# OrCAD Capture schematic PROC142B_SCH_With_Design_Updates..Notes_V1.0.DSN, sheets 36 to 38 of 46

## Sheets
36 36. MCU HEADER: size C; title: SOC-MCU DOMAIN IO, OSC0 AND SOC-MCU IO HEADER
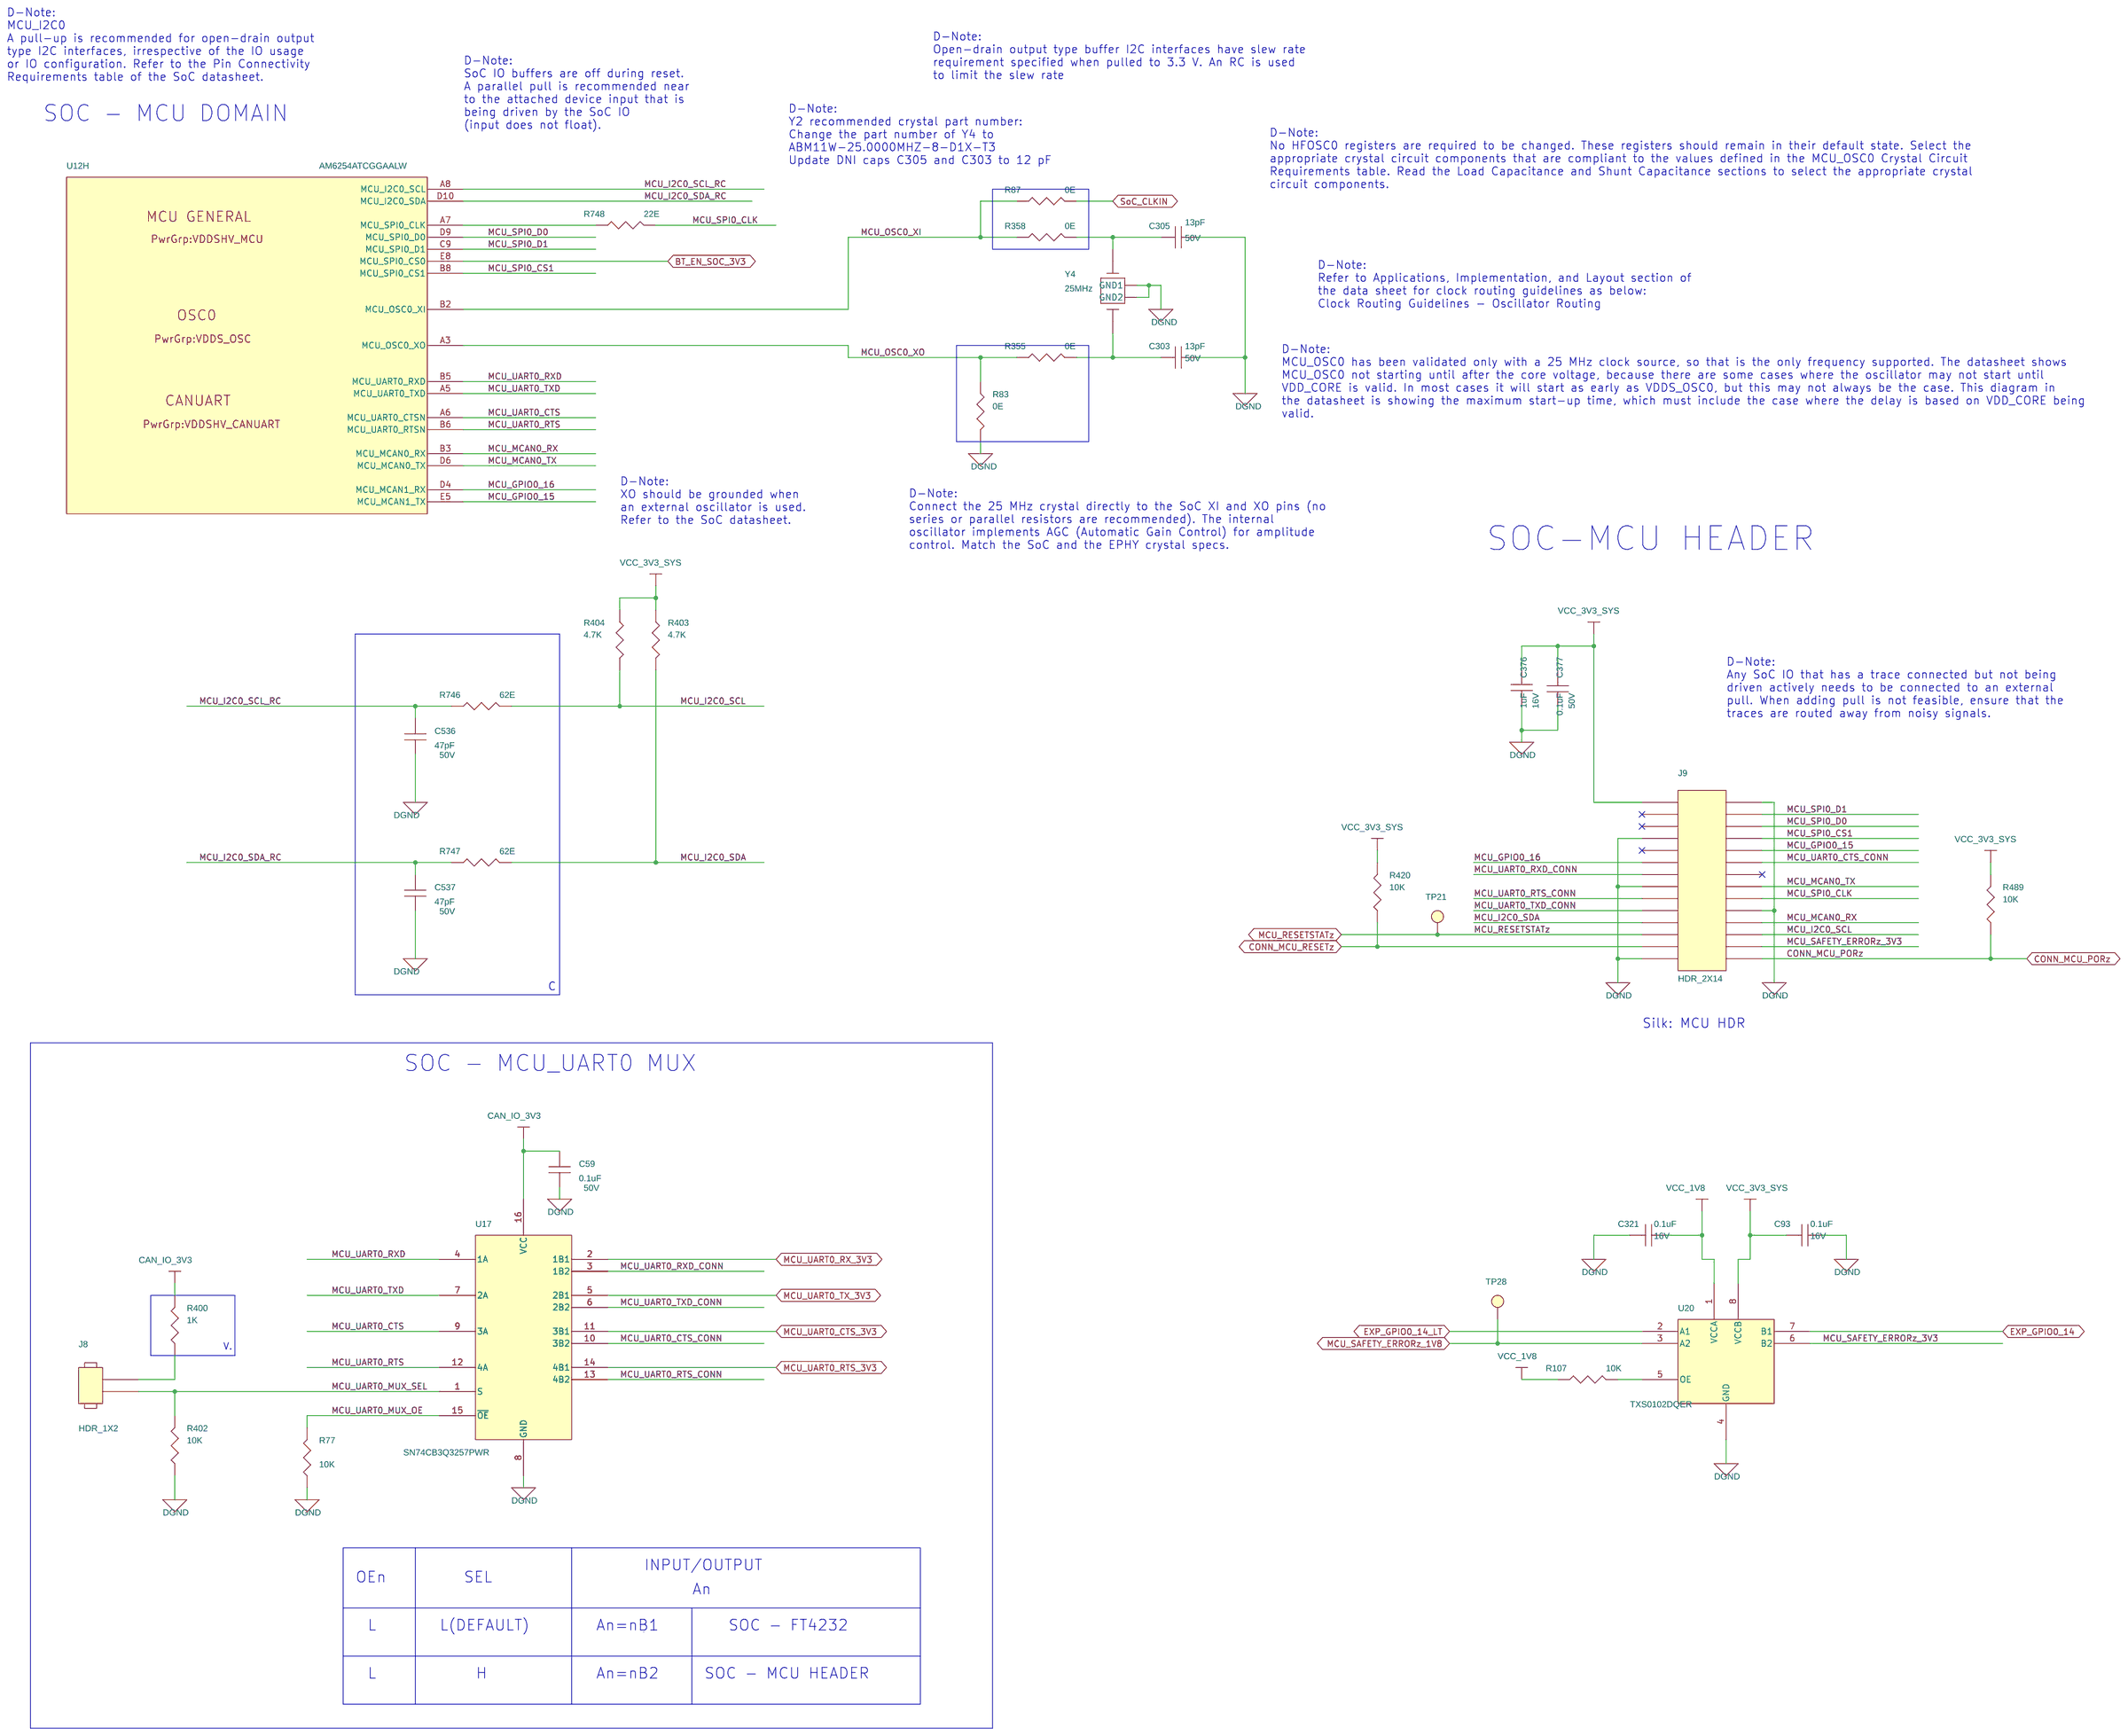
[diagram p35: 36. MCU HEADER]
37 37. USB0 TYPE-C DRP: size C; title: USB0 TYPE-C DRP
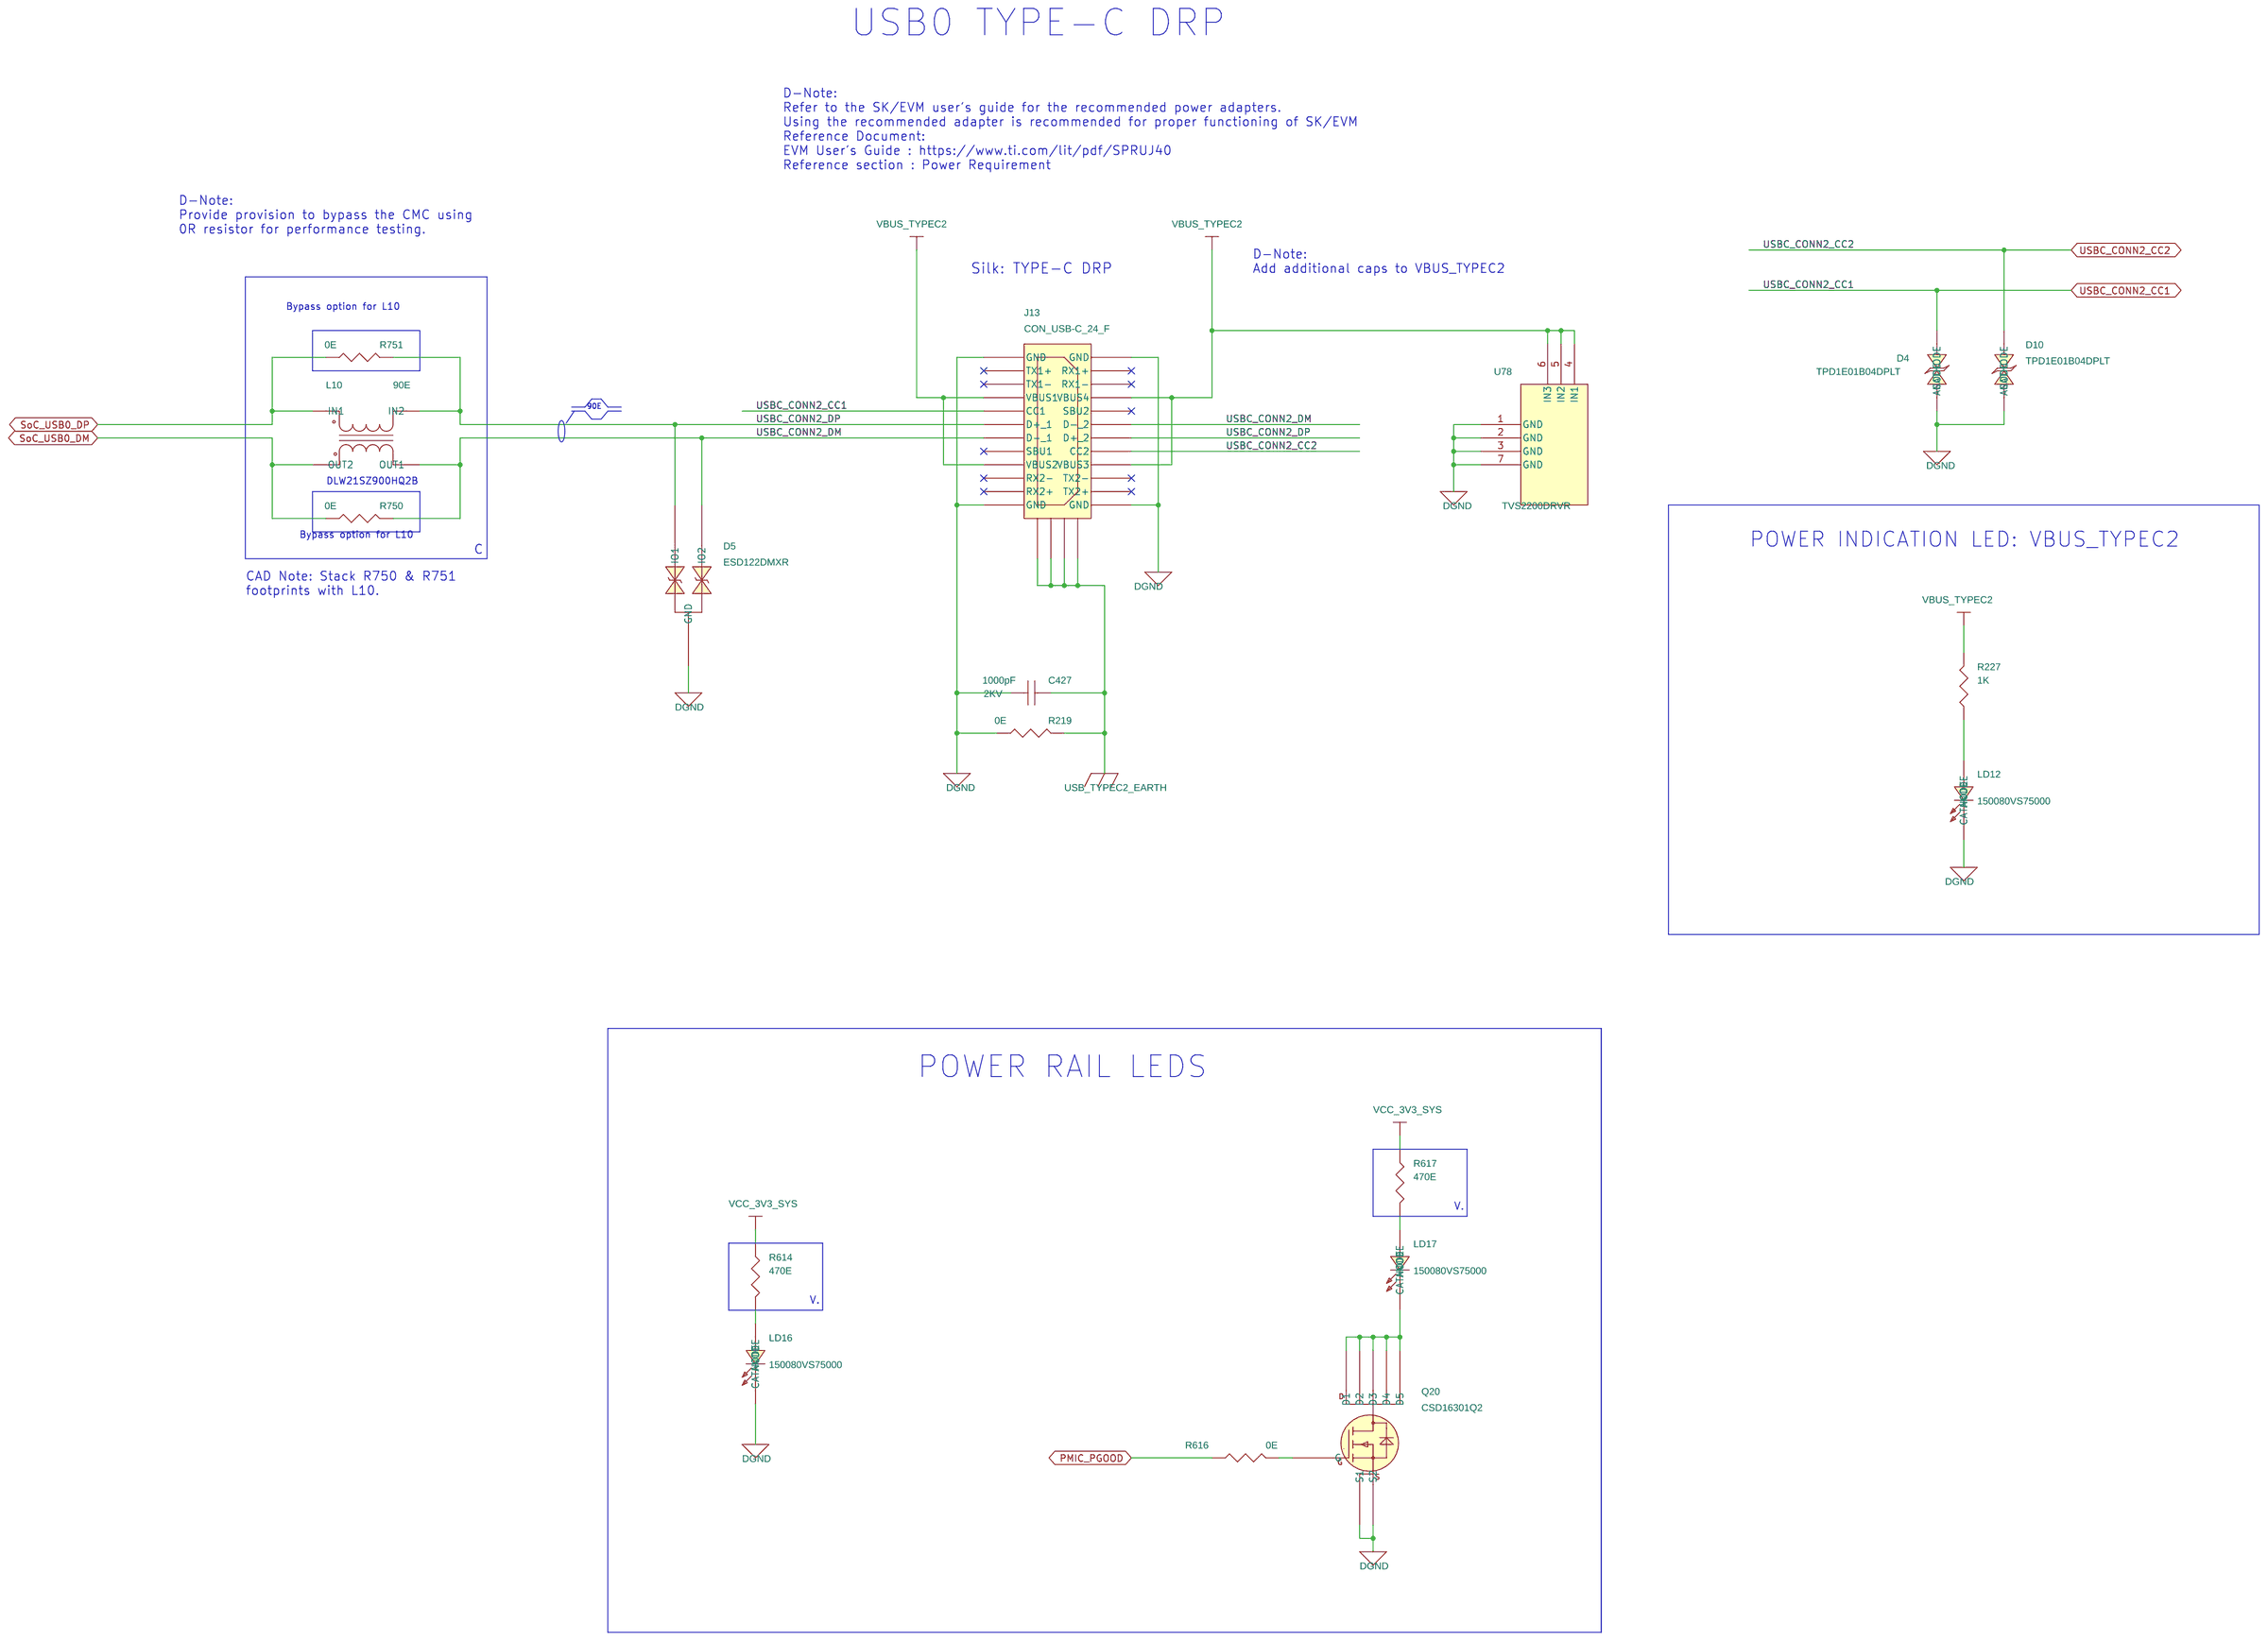
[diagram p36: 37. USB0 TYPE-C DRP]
38 38. USB1 TYPE A: size C; title: SOC USB INTERFACE, USB1 TYPE-A CONNECTOR, POWER SWITCH
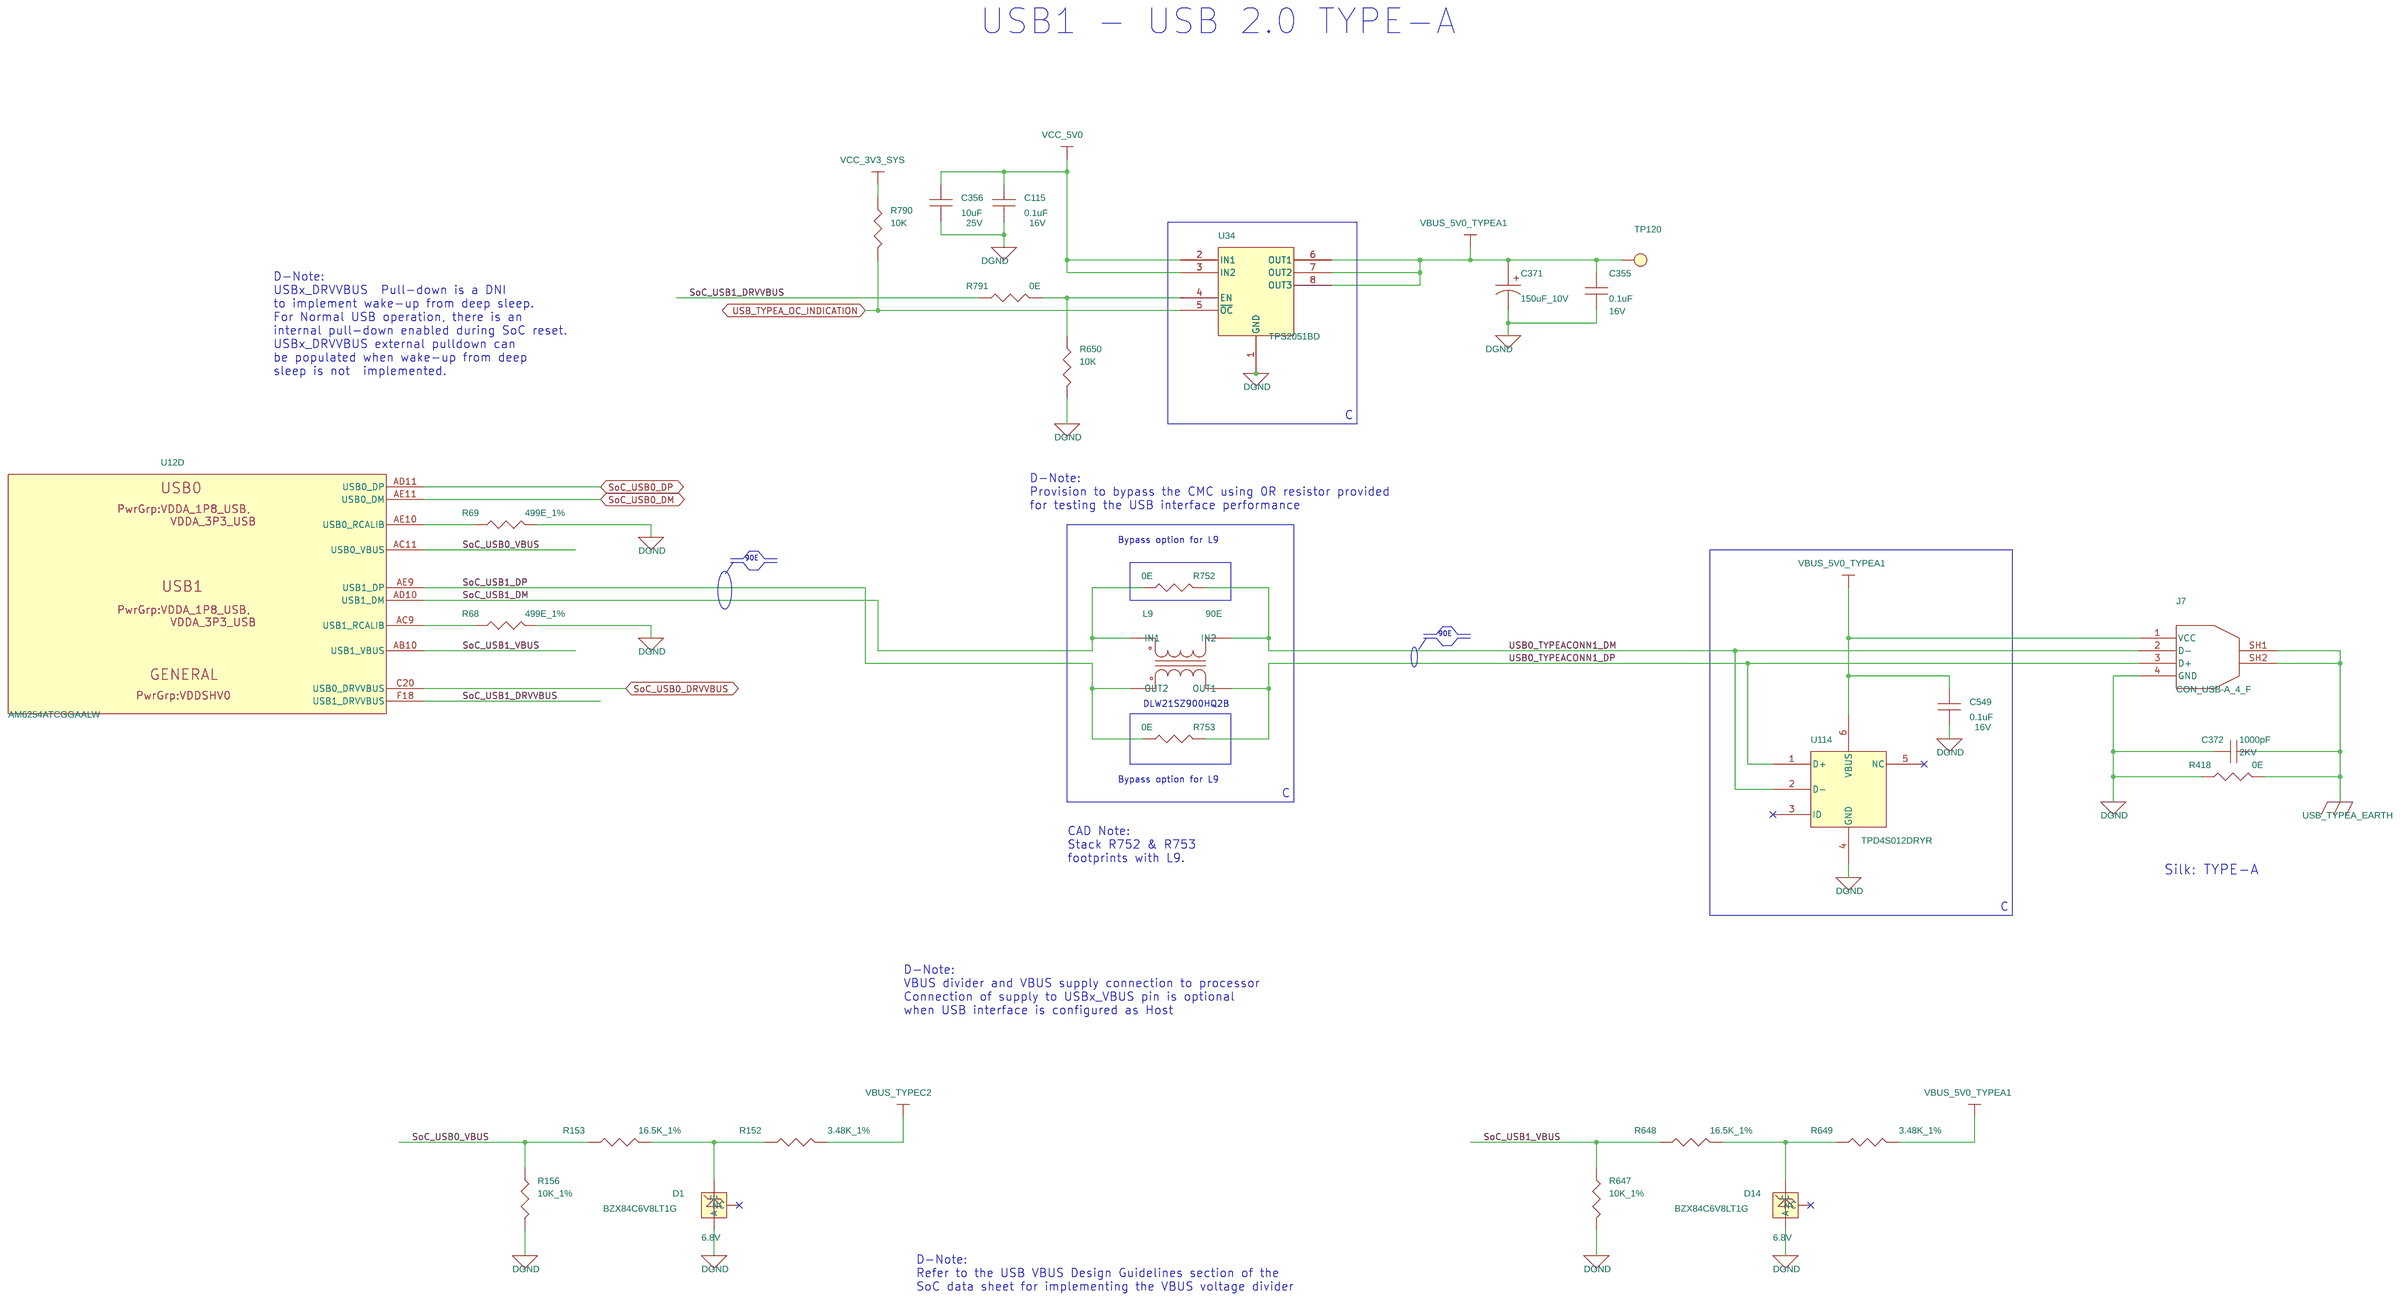
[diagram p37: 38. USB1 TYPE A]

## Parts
sheet 36. MCU HEADER
C59  0.1uF  [CAP0402_0-75]
C93  0.1uF  [CAP0201_0-5]
C303  13pF  [CAP0402_0-75]
C305  13pF  [CAP0402_0-75]
C321  0.1uF  [CAP0201_0-5]
C376  1uF  [CAP0201_0-5]
C377  0.1uF  [CAP0402_0-75]
C536  47pF  [CAP0201_0-5]
C537  47pF  [CAP0201_0-5]
J8  HDR_1X2  [HDR_1X2_90120-0122_S_T_5-6]
J9  HDR_2X14  [HDR_14X2_100_S_T]
R77  10K  [RES0201_0-5]
R83  0E  [RES0201_0-5]
R87  0E  [RES0201_0-5]
R107  10K  [RES0201_0-5]
R355  0E  [RES0402_0-5]
R358  0E  [RES0402_0-5]
R400  1K  [RES0402_0-5]
R402  10K  [RES0201_0-5]
R403  4.7K  [RES0201_0-5]
R404  4.7K  [RES0201_0-5]
R420  10K  [RES0201_0-5]
R489  10K  [RES0201_0-5]
R746  62E  [RES0201_0-5]
R747  62E  [RES0201_0-5]
R748  22E  [RES0402_0-5]
TP21  TP20_SMD  [TP20_SMD]
TP28  TP20_SMD  [TP20_SMD]
U17  SN74CB3Q3257PWR  [TSSOP16_25-59_205X180]
U20  TXS0102DQER  [X2SON8_TXS0102_40X60_0-4]
Y4  25MHz  [XTAL4_ABM11W_80X70_SMD_0-5]
sheet 37. USB0 TYPE-C DRP
C427  1000pF  [CAP1206_1-75]
D4  TPD1E01B04DPLT  [DIO_DFN0201_0-4]
D5  ESD122DMXR  [X2SON3_ESD122DMX_30X40_0-4]
D10  TPD1E01B04DPLT  [DIO_DFN0201_0-4]
J13  CON_USB-C_24_F  [CON_USBC24_2012670_S_R_S_3-9]
L10  90E  [IND4_DLW21H_90X60_SMD_1-4]
LD12  150080VS75000  [LED_150080VS75000_80X50_SMD_0-8]
LD16  150080VS75000  [LED_150080VS75000_80X50_SMD_0-8]
LD17  150080VS75000  [LED_150080VS75000_80X50_SMD_0-8]
Q20  CSD16301Q2  [WSON6_CSD13202Q2_80X80_0-8]
R219  0E  [RES0603_0-75]
R227  1K  [RES0402_0-5]
R614  470E  [RES0402_0-5]
R616  0E  [RES0402_0-5]
R617  470E  [RES0402_0-5]
R750  0E  [RES0402_0-5]
R751  0E  [RES0402_0-5]
U78  TVS2200DRVR  [SON6_25-59_85X85_0-8]
sheet 38. USB1 TYPE A
C115  0.1uF  [CAP0201_0-5]
C355  0.1uF  [CAP0201_0-5]
C356  10uF  [CAP0603_1]
C371  150uF_10V  [CAPT7343D_3-25]
C372  1000pF  [CAP1206_1-75]
C549  0.1uF  [CAP0201_0-5]
D1  BZX84C6V8LT1G  [SOT23-123_1-2]
D14  BZX84C6V8LT1G  [SOT23-123_1-2]
J7  CON_USB-A_4_F  [CON_USBA4_629104151_S_R_S_7-4]
L9  90E  [IND4_DLW21H_90X60_SMD_1-4]
R68  499E_1%  [RES0402_0-5]
R69  499E_1%  [RES0402_0-5]
R152  3.48K_1%  [RES0201_0-5]
R153  16.5K_1%  [RES0402_0-5]
R156  10K_1%  [RES0201_0-5]
R418  0E  [RES0603_0-75]
R647  10K_1%  [RES0201_0-5]
R648  16.5K_1%  [RES0402_0-5]
R649  3.48K_1%  [RES0201_0-5]
R650  10K  [RES0201_0-5]
R752  0E  [RES0402_0-5]
R753  0E  [RES0402_0-5]
R790  10K  [RES0201_0-5]
R791  0E  [RES0201_0-5]
TP120  TP20_SMD  [TP20_SMD]
U34  TPS2051BD  [SOIC8_1-8]
U114  TPD4S012DRYR  [SON6_SN74LVC2G17_40X60_0-6]
sheet 43. HDMI INTERFACE
U12  AM6254ATCGGAALW  [BGA425_19-68_510X510_0-7]  (sections A,B,C,D,E,F,G,H,I,J,K,L,M,N,O,P,Q,R)

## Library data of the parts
C59 C377 = CAP: CAP CERAMIC 0.1uF 50V 10% X7R 0402; Alt_Mfr_name: YAGEO AMERICA; Alt_Mfr_part_number: CC0402KRX5R8BB104; Chkd/date: MANIRAJA/261020; Crtd /date: ALVY/211020; Custom_Duty: 15%; Customs_HS_Code: 85322990; Distributor_name: DIGIKEY; Distributor_part_number: 490-10700-1-ND; Footprint Path: Y:\MIS_DATABASE\Library\ALTIUM_TOOL\PCB_FOOTPRINTS\Altium_Footprint_Lib.PcbLib; Height: 0.55MM; Library Path: Y:\MIS_DATABASE\Library\ALTIUM_TOOL\SCHEMATICS_PARTS\MS_DISCRETE_Library.schlib; Mfr_name: MURATA; Mfr_part_number: GRM155R71H104KE14D; Mistral Part No: 120011100014-R; Package: 0402; Part_type: CAPACITORS\CERAMIC; Project: J7_CP; RoHS: RoHS; Temperature: -55°C+125°C; Tolerance: 10%; Voltage: 50V; Wattage: NA; Weight: 3.1mg; Datasheet: Y:\MIS_DATABASE\DATASHEETS\CAPACITORS\GRM155R71H104KE14.PDF
C93 C321 = CAP: CAP CERAMIC 0.1uF 16V 10% X5R 0201; Alt_Mfr_name: YAGEO AMERICA; Alt_Mfr_part_number: CC0402KRX5R8BB104; Chkd/date: MANIRAJA/230118; Crtd /date: MANIRAJA/230118; Custom_Duty: 15%; Customs_HS_Code: 85322990; Distributor_name: DIGIKEY; Distributor_part_number: 490-14305-1-ND; Footprint Path: Y:\MIS_DATABASE\Library\ALTIUM_TOOL\PCB_FOOTPRINTS\Altium_Footprint_Lib.PcbLib; Height: 0.33MM; Library Path: Y:\MIS_DATABASE\Library\ALTIUM_TOOL\SCHEMATICS_PARTS\MS_DISCRETE_Library.schlib; Mfr_name: MURATA; Mfr_part_number: GRM033R61C104KE14D; Mistral Part No: 120009030072-R; Package: 0201; Part_type: CAPACITORS\CERAMIC; Project: TI_MAXIE_CPB; RoHS: RoHS; Temperature: -55°C+85°C; Tolerance: 10%; Voltage: 16V; Wattage: NA; Weight: 0.33mg; Datasheet: Y:\MIS_DATABASE\DATASHEETS\CAPACITORS\GRM033R61C104KE14.PDF
C303 C305 = CAP: CAP CERAMIC 13pF 50V 5% C0G(NP0) 0402; Chkd/date: VASANTHA/090317; Crtd /date: MANIRAJA/090317; Custom_Duty: 15%; Customs_HS_Code: 85322990; Distributor_name: DIGIKEY; Distributor_part_number: 490-5925-1-ND; Footprint Path: Y:\MIS_DATABASE\Library\ALTIUM_TOOL\PCB_FOOTPRINTS\Altium_Footprint_Lib.PcbLib; Height: 0.55MM; Library Path: Y:\MIS_DATABASE\Library\ALTIUM_TOOL\SCHEMATICS_PARTS\MS_DISCRETE_Library.schlib; Mfr_name: MURATA; Mfr_part_number: GRM1555C1H130JA01D; Mistral Part No: 120017030004-R; Package: 0402; Part_type: CAPACITORS\CERAMIC; Project: SD820_NANO_SOM; RoHS: RoHS; Temperature: -55°C+125°C; Tolerance: 5%; Voltage: 50V; Wattage: NA; Weight: 6mg; Datasheet: Y:\MIS_DATABASE\DATASHEETS\CAPACITORS\MURATA-GXX-SER_NOV17.PDF
C376 = CAP: CAP CERAMIC 1uF 16V 20% X5R 0201; Chkd/date: MANIRAJA/300520; Crtd /date: ALVY/260520; Custom_Duty: 15%; Customs_HS_Code: 85322990; Distributor_name: DIGIKEY; Distributor_part_number: 490-18654-1-ND; Footprint Path: Y:\MIS_DATABASE\Library\ALTIUM_TOOL\PCB_FOOTPRINTS\Altium_Footprint_Lib.PcbLib; Height: 0.39MM; Library Path: Y:\MIS_DATABASE\Library\ALTIUM_TOOL\SCHEMATICS_PARTS\MS_DISCRETE_Library.schlib; Mfr_name: MURATA; Mfr_part_number: GRM033R61C105ME15D; Mistral Part No: 120018090038-R; Package: 0201; Part_type: CAPACITORS\CERAMIC; Project: QCS610_NANOSOM; RoHS: RoHS; Temperature: -55°C+85°C; Tolerance: 20%; Voltage: 16V; Wattage: NA; Weight: 0.33mg; Datasheet: Y:\MIS_DATABASE\DATASHEETS\CAPACITORS\GRM033R61C105ME15.PDF
C536 C537 = CAP: CAP CERAMIC 47pF 50V 5% C0G(NP0) AUTO 0201; Chkd/date: MANIRAJA/311221; Crtd /date: ALVY/301221; Custom_Duty: 15%; Customs_HS_Code: 85322990; Distributor_name: MOUSER; Distributor_part_number: 81-GRT0335C1H470JA2D; Footprint Path: Y:\MIS_DATABASE\Library\ALTIUM_TOOL\PCB_FOOTPRINTS\Altium_Footprint_Lib.PcbLib; Height: 0.33MM; Library Path: Y:\MIS_DATABASE\Library\ALTIUM_TOOL\SCHEMATICS_PARTS\MS_DISCRETE_Library.schlib; Mfr_name: MURATA; Mfr_part_number: GRT0335C1H470JA02D; Mistral Part No: 120021120018-R; Package: 0201; Part_type: CAPACITORS\CERAMIC; Project: AM62Q_SKEVM_BRD; RoHS: RoHS; Temperature: -55°C+125°C; Tolerance: 5%; Voltage: 50V; Wattage: NA; Weight: 0.33mg; Datasheet: Y:\MIS_DATABASE\DATASHEETS\CAPACITORS\GRT0335C1H470JA02.PDF
J8 = HEADER_2X1: CON HDR 1X2 2.54MM PITCH ST TH; Chkd/date: NAVEED/210714; Crtd /date: USMAN/031012; Custom_Duty: 24%; Customs_HS_Code: 85369090; Distributor_name: DIGIKEY; Distributor_part_number: WM8072-ND; Footprint Path: Y:\MIS_DATABASE\Library\ALTIUM_TOOL\PCB_FOOTPRINTS\Altium_Footprint_Lib.PcbLib; Height: 5.60MM; Library Path: Y:\MIS_DATABASE\Library\ALTIUM_TOOL\SCHEMATICS_PARTS\MS_CONNECTOR_Library.schlib; Mfr_name: MOLEX; Mfr_part_number: 90120-0122; Mistral Part No: 150012100005-R; Package: THRU-HOLE; Part_type: CONNECTOR\HEADERS; Project: NPOL_FEP; RoHS: RoHS; Temperature: -55°C+125°C; Tolerance: NA; Voltage: NA; Wattage: NA; Weight: 122mg; Datasheet: Y:\MIS_DATABASE\DATASHEETS\CONNECTORS\90120-XX.PDF
J9 = HEADER_14x2: CON HDR 2X14 2.54MM PITCH ST TH; Chkd/date: NAVEED/280515; Crtd /date: VASANTHA/111114; Custom_Duty: 0.24; Customs_HS_Code: 85369090; Distributor_name: DIGIKEY; Distributor_part_number: S2012EC-14-ND; Height: 8.34MM; Mfr_name: SULLINS; Mfr_part_number: PREC014DAAN-RC; Mistral Part No: 150014110005-R; Package: THRU-HOLE; Part_type: CONNECTOR\HEADERS; Project: GALILEO_EVM; RoHS: RoHS; Temperature: -40°C+105°C; Tolerance: NA; Voltage: NA; Wattage: NA; Weight: NA; Datasheet: Y:\MIS_DATABASE\DATASHEETS\CONNECTORS\PRXXXN-RC.PDF
R77 R107 R402 R420 R489 R650 R790 = RESISTOR: RES 10K 1/20W 5% 0201; Chkd/date: MANIRAJA/050517; Crtd /date: MANIRAJA/050517; Custom_Duty: 15%; Customs_HS_Code: 85332119; Distributor_name: DIGIKEY; Distributor_part_number: 311-10KNCT-ND; Footprint Path: Y:\MIS_DATABASE\Library\ALTIUM_TOOL\PCB_FOOTPRINTS\Altium_Footprint_Lib.PcbLib; Height: 0.26MM; Library Path: Y:\MIS_DATABASE\Library\ALTIUM_TOOL\SCHEMATICS_PARTS\MS_DISCRETE_Library.schlib; Mfr_name: YAGEO AMERICA; Mfr_part_number: RC0201JR-0710KL; Mistral Part No: 110010070051-R; Package: 0201; Part_type: RESISTORS\FIXED; Project: GOLDEN-I LITE; RoHS: RoHS; Temperature: -55°C+125°C; Tolerance: 5%; Voltage: NA; Wattage: 1/20W; Weight: 0.17mg; Datasheet: Y:\MIS_DATABASE\DATASHEETS\RESISTORS\RCXXXXL-SER_MAR18.PDF
R83 R87 R791 = RESISTOR: RES 0E 1/20W 5% 0201; Chkd/date: NAVEED/301214; Crtd /date: MUDDU/120710; Custom_Duty: 15%; Customs_HS_Code: 85332119; Distributor_name: DIGIKEY; Distributor_part_number: 311-0.0NCT-ND; Footprint Path: Y:\MIS_DATABASE\Library\ALTIUM_TOOL\PCB_FOOTPRINTS\Altium_Footprint_Lib.PcbLib; Height: 0.26MM; Library Path: Y:\MIS_DATABASE\Library\ALTIUM_TOOL\SCHEMATICS_PARTS\MS_DISCRETE_Library.schlib; Mfr_name: YAGEO AMERICA; Mfr_part_number: RC0201JR-070RL; Mistral Part No: 110010070067-R; Package: 0201; Part_type: RESISTORS\FIXED; Project: PB_BUGBASE; RoHS: RoHS; Temperature: -55°C+125°C; Tolerance: 5%; Voltage: NA; Wattage: 1/20W; Weight: 0.17mg; Datasheet: Y:\MIS_DATABASE\DATASHEETS\RESISTORS\RCXXXXL-SER_MAR18.PDF
R355 R358 R616 R750-R753 = RESISTOR: RES 0E 1/16W JUMPER 0402; Chkd/date: VASANTHA/201216; Crtd /date: MUDDU/190810; Custom_Duty: 15%; Customs_HS_Code: 85332119; Distributor_name: DIGIKEY; Distributor_part_number: 541-0.0JCT-ND; Footprint Path: Y:\MIS_DATABASE\Library\ALTIUM_TOOL\PCB_FOOTPRINTS\Altium_Footprint_Lib.PcbLib; Height: 0.40MM; Library Path: Y:\MIS_DATABASE\Library\ALTIUM_TOOL\SCHEMATICS_PARTS\MS_DISCRETE_Library.schlib; Mfr_name: VISHAY; Mfr_part_number: CRCW04020000Z0ED; Mistral Part No: 110010080019-R; Package: 0402; Part_type: RESISTORS\FIXED; Project: PB_BUGBASE; RoHS: RoHS; Temperature: -55°C+155°C; Tolerance: NA; Voltage: NA; Wattage: 1/16W; Weight: 0.65mg; Datasheet: Y:\MIS_DATABASE\DATASHEETS\RESISTORS\CRCW0603.PDF
R227 R400 = RESISTOR: RES 1K 1/10W 5% 0402; Chkd/date: VASANTHA/201216; Crtd /date: MAZHAR/230805; Custom_Duty: 15%; Customs_HS_Code: 85332119; Distributor_name: DIGIKEY; Distributor_part_number: P1.0KJCT-ND; Footprint Path: Y:\MIS_DATABASE\Library\ALTIUM_TOOL\PCB_FOOTPRINTS\Altium_Footprint_Lib.PcbLib; Height: 0.40MM; Library Path: Y:\MIS_DATABASE\Library\ALTIUM_TOOL\SCHEMATICS_PARTS\MS_DISCRETE_Library.schlib; Mfr_name: PANASONIC-ECG; Mfr_part_number: ERJ-2GEJ102X; Mistral Part No: 110009030400-R; Package: 0402; Part_type: RESISTORS\FIXED; Project: HSE; RoHS: RoHS; Temperature: -55°C+155°C; Tolerance: 5%; Voltage: NA; Wattage: 1/10W; Weight: 0.8mg; Datasheet: Y:\MIS_DATABASE\DATASHEETS\RESISTORS\PAN-ERJSER_NOV17.PDF
R403 R404 = RESISTOR: RES 4.7K 1/20W 5% 0201; Chkd/date: MANIRAJA/200921; Crtd /date: ALVY/200921; Custom_Duty: 15%; Customs_HS_Code: 85332119; Distributor_name: DIGIKEY; Distributor_part_number: 311-4.7KNCT-ND; Footprint Path: Y:\MIS_DATABASE\Library\ALTIUM_TOOL\PCB_FOOTPRINTS\Altium_Footprint_Lib.PcbLib; Height: 0.26MM; Library Path: Y:\MIS_DATABASE\Library\ALTIUM_TOOL\SCHEMATICS_PARTS\MS_DISCRETE_Library.schlib; Mfr_name: YAGEO AMERICA; Mfr_part_number: RC0201JR-074K7L; Mistral Part No: 110021090007-R; Package: 0201; Part_type: RESISTORS\FIXED; Project: TI_AM62x SKEVM_BRD; RoHS: RoHS; Temperature: -55°C+125°C; Tolerance: 5%; Voltage: NA; Wattage: 1/20W; Weight: 0.17mg; Datasheet: Y:\MIS_DATABASE\DATASHEETS\RESISTORS\RCXXXXL-SER_MAR18.PDF
R746 R747 = RESISTOR: RES 62E 1/20W 1% 0201; Chkd/date: PRADEEP/230326; Crtd /date: SHANKARI/230326; Custom_Duty: 15%; Customs_HS_Code: 85332119; Distributor_name: DIGIKEY; Distributor_part_number: P123108CT-ND; Footprint Path: Y:\MIS_DATABASE\Library\ALTIUM_TOOL\PCB_FOOTPRINTS\Altium_Footprint_Lib.PcbLib; Height: 0.26MM; Library Path: Y:\MIS_DATABASE\Library\ALTIUM_TOOL\SCHEMATICS_PARTS\MS_DISCRETE_Library.schlib; Mfr_name: PANASONIC; Mfr_part_number: ERJ-1GNF62R0C; Mistral Part No: 110026030006-R; Package: 0201; Part_type: RESISTORS\FIXED; Project: AM62X_FULTON_REV B; RoHS: RoHS; Temperature: -55°C+125°C; Tolerance: 0.01; Voltage: NA; Wattage: 1/20W; Weight: NA; Datasheet: Y:\MIS_DATABASE\DATASHEETS\RESISTORS\ERJ-1GNF62R0C.PDF
R748 = RESISTOR: RES 22E 1/16W 5% 0402; Chkd/date: ALVY/210122; Crtd /date: TAMILARASU/210122; Custom_Duty: 15%; Customs_HS_Code: 85332119; Distributor_name: DIGIKEY; Distributor_part_number: 311-22JRCT-ND; Footprint Path: Y:\MIS_DATABASE\Library\ALTIUM_TOOL\PCB_FOOTPRINTS\Altium_Footprint_Lib.PcbLib; Height: 0.40MM; Library Path: Y:\MIS_DATABASE\Library\ALTIUM_TOOL\SCHEMATICS_PARTS\MS_DISCRETE_Library.schlib; Manufacturer: YAGEO; Mfr_name: YAGEO AMERICA; Mfr_part_number: RC0402JR-0722RL; Mistral Part No: 110022010018-R; Package: 0402; Part_type: RESISTORS\FIXED; Project: DLRL DIGITAL RECEIVER_BRD; RoHS: RoHS; Temperature: -55°C+155°C; Tolerance: 5%; Voltage: NA; Wattage: 1/16W; Weight: 0.65mg; Datasheet: Y:\MIS_DATABASE\DATASHEETS\RESISTORS\RCXXXXP-SER_SEP18.PDF
TP21 TP28 TP120 = TESTPOINT: TESTPOINT CIR 20 SMD; Chkd/date: SHREESHAIL/171006; Crtd /date: MAZHAR/171006; Custom_Duty: NA; Customs_HS_Code: NA; Distributor_name: NA; Distributor_part_number: NA; Footprint Path: Y:\MIS_DATABASE\Library\ALTIUM_TOOL\PCB_FOOTPRINTS\Altium_Footprint_Lib.PcbLib; Height: NA; Library Path: Y:\MIS_DATABASE\Library\ALTIUM_TOOL\SCHEMATICS_PARTS\MS_DISCRETE_Library.schlib; MECHANICAL 3D STEP FILE: NA; Mfr_name: LOCAL; Mistral Part No: NA; Package: SMD; Project: BT MODULE_CSRBC04; RoHS: NA; Temperature: NA; Tolerance: NA; Voltage: NA; Wattage: NA; Weight: NA; Datasheet: NA
U17 = SN74CB3Q3257PWR_TSSOP16: IC 4BIT 1-OF-2 FET MULTIPLEXER/DEMULTIPLEXER TSSOP16; Chkd/date: SUHAS/251010; Crtd /date: USMAN/060109; Custom_Duty: 15%; Customs_HS_Code: 85423100; Distributor_name: DIGIKEY; Distributor_part_number: 296-19138-1-ND; Height: 1.20MM; Mfr_name: TEXAS INSTRUMENTS; Mistral Part No: 141009030117-R; Package: TSSOP16; Part_type: ICS\DIGITAL\COMBINATIONAL; Project: OMAP_EVM; RoHS: Sb/ Br FREE; Temperature: -40°C+85°C; Datasheet: Y:\MIS_DATABASE\DATASHEETS\ICS\DIGITAL\COMBINATIONAL\SN74CB3Q3257.PDF
U20 = TXS0102DQX_SON8: IC 2-BIT BI-DIR VOLTAGE-LEVEL TRANSLATOR FOR OPEN-DRAIN AND PUSH-PULL X2SON8; Chkd/date: MANIRAJA/010719; Crtd /date: CHAITHANYA230512; Custom_Duty: 15%; Customs_HS_Code: 85423100; Distributor_name: DIGIKEY; Distributor_part_number: 296-28368-1-ND; Footprint Path: Y:\MIS_DATABASE\Library\ALTIUM_TOOL\PCB_FOOTPRINTS\Altium_Footprint_Lib.PcbLib; Height: 0.40MM; Library Path: Y:\MIS_DATABASE\Library\ALTIUM_TOOL\SCHEMATICS_PARTS\MS_MISCINTERFACE_Library.schlib; Mfr_name: TEXAS INSTRUMENTS; Mistral Part No: 141012050010-R; Package: X2SON8; Part_type: ICS\INTERFACE\LEVEL TRANSLATOR; Project: GEN_3-8_DB; RoHS: RoHS; Temperature: -40°C+85°C; Tolerance: NA; Voltage: NA; Wattage: NA; Weight: 1.2mg; Datasheet: Y:\MIS_DATABASE\DATASHEETS\ICS\INTERFACE\TXS0102-SER.PDF
Y4 = CRY4_ABM8G: CRY 25MHz 8pF SMD; Crtd /date: SHANKARI/041125; Custom_Duty: 24%; Customs_HS_Code: 85439000; Distributor_name: DIGIKEY; Distributor_part_number: 535-13853-1-ND; Footprint Path: Y:\MIS_DATABASE\Library\ALTIUM_TOOL\PCB_FOOTPRINTS\Altium_Footprint_Lib.PcbLib; Height: 0.50MM; Library Path: Y:\MIS_DATABASE\Library\ALTIUM_TOOL\SCHEMATICS_PARTS\MS_DISCRETE_Library.schlib; Mfr_name: ABRACON CORPORATION; Mfr_part_number: ABM11W-25.0000MHZ-8-D1X-T3; Mistral Part No: 130025110002-R; Package: SMD; Part_type: CRYSTAL; Project: AM62X_SK_FULTON; RoHS: RoHS; Temperature: -40°C+85°C; Tolerance: NA; Voltage: NA; Wattage: NA; Weight: NA; Datasheet: Y:\MIS_DATABASE\DATASHEETS\MISC\CRY_OSC\ABM11W.PDF
C372 C427 = CAP: CAP CERAMIC 1000pF 2KV 10% X7R 1206; Chkd/date: SHREESHAIL/291106; Crtd /date: MAZHAR/281106; Custom_Duty: 15%; Customs_HS_Code: 85322990; Distributor_name: DIGIKEY; Distributor_part_number: 478-2956-1-ND; Footprint Path: Y:\MIS_DATABASE\Library\ALTIUM_TOOL\PCB_FOOTPRINTS\Altium_Footprint_Lib.PcbLib; Height: 1.52MM; Library Path: Y:\MIS_DATABASE\Library\ALTIUM_TOOL\SCHEMATICS_PARTS\MS_DISCRETE_Library.schlib; Mfr_name: AVX CORPORATION; Mfr_part_number: 1206GC102KAT1A; Mistral Part No: 120015080006-R; Package: 1206; Part_type: CAPACITORS\CERAMIC; Project: ADR1B; RoHS: RoHS; Temperature: -55°C+125°C; Tolerance: 10%; Voltage: 2KV; Wattage: NA; Weight: 16.2mg; Datasheet: Y:\MIS_DATABASE\DATASHEETS\CAPACITORS\AVX_HV-MLC.PDF
D4 D10 = DIODE_TVS_DUAL: DIODE 1CH ESD PROTECTION FOR USB TYPE-C AND THUNDERBOLT3 X2SON2; Chkd/date: MANIRAJA/230920; Crtd /date: ALVY/230920; Custom_Duty: 15%; Customs_HS_Code: 85412900; Distributor_name: DIGIKEY; Distributor_part_number: 296-44484-1-ND; Footprint Path: Y:\MIS_DATABASE\Library\ALTIUM_TOOL\PCB_FOOTPRINTS\Altium_Footprint_Lib.PcbLib; Height: 0.32MM; Library Path: Y:\MIS_DATABASE\Library\ALTIUM_TOOL\SCHEMATICS_PARTS\MS_DISCRETE_Library.schlib; Mfr_name: TEXAS INSTRUMENTS; Mistral Part No: 130020090037-R; Package: X2SON2; Part_type: DIODE\TVS; Project: AM64X_SKEVM; RoHS: RoHS; Temperature: -40°C+125°C; Tolerance: NA; Voltage: NA; Wattage: NA; Weight: 0.2mg; Datasheet: Y:\MIS_DATABASE\DATASHEETS\DISCRETES\DIODES\TPD1E01B04.PDF
D5 = DIODE_ESD122DMXR: DIODE 2-CH ESD PROTECTION FOR USB TYPE-C AND HDMI 2.0 X2SON-3; Chkd/date: MANIRAJA/140817; Crtd /date: MANIRAJA/140817; Custom_Duty: 15%; Customs_HS_Code: 85412900; Distributor_name: DIGIKEY; Distributor_part_number: ESD122DMXR-ND; Height: 0.40MM; Mfr_name: TEXAS INSTRUMENTS; Mistral Part No: 130017080015-R; Package: X2SON-3; Part_type: DIODE\TVS; Project: TI_SVB_CONTROLLER CARD; RoHS: RoHS; Temperature: -40°C+125°C; Tolerance: NA; Voltage: NA; Wattage: NA; Weight: NA; Datasheet: Y:\MIS_DATABASE\DATASHEETS\DISCRETES\DIODES\ESD122XX.PDF
J13 = CON_USB-C_24_1240183621: CON USB-C TYPE 24POS FEMALE RT SMD; Chkd/date: MANIRAJA/050618; Crtd /date: ALVY/040618; Custom_Duty: 24%; Customs_HS_Code: 85369090; Distributor_name: DIGIKEY; Distributor_part_number: WM17992CT-ND; Footprint Path: Y:\MIS_DATABASE\Library\ALTIUM_TOOL\PCB_FOOTPRINTS\Altium_Footprint_Lib.PcbLib; Height: 3.86MM; Library Path: Y:\MIS_DATABASE\Library\ALTIUM_TOOL\SCHEMATICS_PARTS\MS_CONNECTOR_Library.schlib; Mfr_name: MOLEX; Mfr_part_number: 2012670005; Mistral Part No: 150018060002-R; Package: SMD; Part_type: CONNECTOR\USB; Project: TI_J7SVB_USB_ADD-ON-CARD; RoHS: RoHS; Temperature: -40°C+105°C; Tolerance: NA; Voltage: NA; Wattage: NA; Weight: 0.686g; Datasheet: Y:\MIS_DATABASE\DATASHEETS\CONNECTORS\2012670X.PDF
L9 L10 = INDUCTOR_DLW31S: IND COMMON MODE CHOKE 90E 280mA SMD; Chkd/date: MANIRAJA/270619; Crtd /date: MANIRAJA/270619; Custom_Duty: 24%; Customs_HS_Code: 85437099; Distributor_name: NA; Distributor_part_number: NA; Footprint Path: Y:\MIS_DATABASE\Library\ALTIUM_TOOL\PCB_FOOTPRINTS\Altium_Footprint_Lib.PcbLib; Height: 1.40MM; Library Path: Y:\MIS_DATABASE\Library\ALTIUM_TOOL\SCHEMATICS_PARTS\MS_DISCRETE_Library.schlib; Mfr_name: MURATA; Mfr_part_number: DLW21SZ900HQ2B; Mistral Part No: 130019060035-R; Package: SMD; Part_type: INDUCTOR; Project: TI_J7ES_CP; RoHS: RoHS; Temperature: -40°C+105°C; Tolerance: NA; Voltage: NA; Wattage: NA; Weight: 11mg; Datasheet: Y:\MIS_DATABASE\DATASHEETS\DISCRETES\INDUCTORS\DLW21SZ900HQ2B.PDF
LD12 LD16 LD17 = DIODE_LED: DIODE LED BRIGHT GREEN SMD; Chkd/date: MANIRAJA/180820; Crtd /date: ALVY/180820; Custom_Duty: 24%; Customs_HS_Code: 85439000; Distributor_name: DIGIKEY; Distributor_part_number: 732-4986-1-ND; Footprint Path: Y:\MIS_DATABASE\Library\ALTIUM_TOOL\PCB_FOOTPRINTS\Altium_Footprint_Lib.PcbLib; Height: 0.80MM; Library Path: Y:\MIS_DATABASE\Library\ALTIUM_TOOL\SCHEMATICS_PARTS\MS_OPTO_Library.schlib; Mfr_name: WURTH ELECTRONICS; Mistral Part No: 130020080012-R; Package: SMD; Part_type: OPTO\LED; Project: AM64x_EVM_BRD; RoHS: RoHS; Temperature: -40°C+85°C; Tolerance: NA; Voltage: NA; Wattage: NA; Weight: 10mg; Datasheet: Y:\MIS_DATABASE\DATASHEETS\DISCRETES\LEDS\150080VS75000.PDF
Q20 = MOSFET_CSD17313Q2: IC MOSFET N-CHANNEL NEXFET 25V WSON6; Chkd/date: ALVY/071220; Crtd /date: MANIRAJA/071220; Custom_Duty: 15%; Customs_HS_Code: 85423100; Distributor_name: DIGIKEY; Distributor_part_number: 296-25260-1-ND; Footprint Path: Y:\MIS_DATABASE\Library\ALTIUM_TOOL\PCB_FOOTPRINTS\Altium_Footprint_Lib.PcbLib; Height: 0.80MM; Library Path: Y:\MIS_DATABASE\Library\ALTIUM_TOOL\SCHEMATICS_PARTS\MS_MOSFET_Library.schlib; Mfr_name: TEXAS INSTRUMENTS; Mistral Part No: 142020120008-R; Package: WSON6; Part_type: ICS\POWER\MOSFET; Project: TI_AM243x LP EVM; RoHS: RoHS; Temperature: -55°C+150°C; Tolerance: NA; Voltage: NA; Wattage: NA; Weight: 8.7mg; Datasheet: Y:\MIS_DATABASE\DATASHEETS\ICS\POWER\CSD16301Q2.PDF
R219 R418 = RESISTOR: RES 0E 1/10W 5% 0603; Chkd/date: MANIRAJA/051217; Crtd /date: BAVISH/180211; Custom_Duty: 15%; Customs_HS_Code: 85332119; Distributor_name: DIGIKEY; Distributor_part_number: 311-0.0GRCT-ND; Footprint Path: Y:\MIS_DATABASE\Library\ALTIUM_TOOL\PCB_FOOTPRINTS\Altium_Footprint_Lib.PcbLib; Height: 0.55MM; Library Path: Y:\MIS_DATABASE\Library\ALTIUM_TOOL\SCHEMATICS_PARTS\MS_DISCRETE_Library.schlib; Manufacturer: YAGEO AMERICA; Mfr_name: PANASONIC-ECG; Mfr_part_number: RC0603JR-070RL; Mistral Part No: 110011020013-R; Package: 0603; Part_type: RESISTORS\FIXED; Project: KENNEL; RoHS: RoHS; Temperature: -55°C+155°C; Tolerance: 5%; Voltage: NA; Wattage: 1/10W; Weight: 2mg; Datasheet: Y:\MIS_DATABASE\DATASHEETS\RESISTORS\RCXXXXL-SER_MAR18.PDF
R614 R617 = RESISTOR: RES 470E 1/10W 5% 0402; Chkd/date: SHREESHAIL/24050; Crtd /date: MAZHAR/260706; Custom_Duty: 15%; Customs_HS_Code: 85332119; Distributor_name: DIGIKEY; Distributor_part_number: P470JCT-ND; Footprint Path: Y:\MIS_DATABASE\Library\ALTIUM_TOOL\PCB_FOOTPRINTS\Altium_Footprint_Lib.PcbLib; Height: 0.40MM; Library Path: Y:\MIS_DATABASE\Library\ALTIUM_TOOL\SCHEMATICS_PARTS\MS_DISCRETE_Library.schlib; Mfr_name: PANASONIC-ECG; Mfr_part_number: ERJ-2GEJ471X; Mistral Part No: 110009030859-R; Package: 0402; Part_type: RESISTORS\FIXED; Project: POWERBOX; RoHS: RoHS; Temperature: -55°C+155°C; Tolerance: 5%; Voltage: NA; Wattage: 1/10W; Weight: 0.8mg; Datasheet: Y:\MIS_DATABASE\DATASHEETS\RESISTORS\PAN-ERJSER_NOV17.PDF
U78 = TVS2200_WSON6: IC 22V FLAT-CLAMP SURGE PROTECTION DEVICE WSON6; Chkd/date: MANIRAJA/011021; Crtd /date: ALVY/011021; Custom_Duty: 15%; Customs_HS_Code: 85423100; Distributor_name: DIGIKEY; Distributor_part_number: 296-52187-1-ND; Footprint Path: Y:\MIS_DATABASE\Library\ALTIUM_TOOL\PCB_FOOTPRINTS\Altium_Footprint_Lib.PcbLib; Height: 0.80MM; Library Path: Y:\MIS_DATABASE\Library\ALTIUM_TOOL\SCHEMATICS_PARTS\MS_MISCPOWER_Library.schlib; Mfr_name: TEXAS INSTRUMENTS; Mistral Part No: 142021100001-R; Package: WSON6; Part_type: ICS\POWER; Project: TI_AM62x SKEVM_BRD; RoHS: RoHS; Temperature: -40°C+125°C; Tolerance: NA; Voltage: NA; Wattage: NA; Weight: 12mg; Datasheet: Y:\MIS_DATABASE\DATASHEETS\ICS\POWER\TVS2200.PDF
C115 C355 C549 = CAP: CAP CERAMIC 0.1uF 16V 10% X5R 0201; Chkd/date: PRADEEP/130623; Crtd /date: PRADEEP/130623; Custom_Duty: 15%; Customs_HS_Code: 85322990; Distributor_name: NA; Distributor_part_number: NA; Footprint Path: Y:\MIS_DATABASE\Library\ALTIUM_TOOL\PCB_FOOTPRINTS\Altium_Footprint_Lib.PcbLib; Height: 0.33MM; Library Path: Y:\MIS_DATABASE\Library\ALTIUM_TOOL\SCHEMATICS_PARTS\MS_DISCRETE_Library.schlib; Mfr_name: MURATA; Mfr_part_number: GRT033R61C104KE01; Mistral Part No: 120022060019-R; Package: 0201; Part_type: CAPACITORS\CERAMIC; Project: AM62P_SK; RoHS: RoHS; Temperature: -55°C+85°C; Tolerance: 10%; Voltage: 16V; Wattage: NA; Weight: 0.33mg; Datasheet: Y:\MIS_DATABASE\DATASHEETS\CAPACITORS\GRT033R61C104KE01XX.PDF
C356 = CAP: CAP CERAMIC 10uF 25V 20% X5R AUTO 0603; Chkd/date: PRADEEP/130623; Crtd /date: PRADEEP/130623; Custom_Duty: 15%; Customs_HS_Code: 85322990; Distributor_name: NA; Distributor_part_number: NA; Footprint Path: Y:\MIS_DATABASE\Library\ALTIUM_TOOL\PCB_FOOTPRINTS\Altium_Footprint_Lib.PcbLib; Height: 1.00MM; Library Path: Y:\MIS_DATABASE\Library\ALTIUM_TOOL\SCHEMATICS_PARTS\MS_DISCRETE_Library.schlib; Mfr_name: MURATA; Mfr_part_number: GRT188R61E106ME13; Mistral Part No: 120022060023-R; Package: 0603; Part_type: CAPACITORS\CERAMIC; Project: AM62P_SK; RoHS: RoHS; Temperature: -55°C+85°C; Tolerance: 20%; Voltage: 25V; Wattage: NA; Weight: 2mg; Datasheet: Y:\MIS_DATABASE\DATASHEETS\CAPACITORS\GRT188R61E106ME13.PDF
C371 = CAP_POL: CAP TANTALUM 150uF 10V 10% ESR 600mE D7343; Chkd/date: ALVY/200921; Crtd /date: MANIRAJA/200921; Custom_Duty: 15%; Customs_HS_Code: 85322990; Distributor_name: DIGIKEY; Distributor_part_number: 718-1960-1-ND; Footprint Path: Y:\MIS_DATABASE\Library\ALTIUM_TOOL\PCB_FOOTPRINTS\Altium_Footprint_Lib.PcbLib; Height: 3.10MM; Library Path: Y:\MIS_DATABASE\Library\ALTIUM_TOOL\SCHEMATICS_PARTS\MS_DISCRETE_Library.schlib; Mfr_name: VISHAY; Mfr_part_number: 293D157X9010D2TE3; Mistral Part No: 120021090007-R; Package: D7343; Part_type: CAPACITORS\TANTALUM; Project: TI_AM62x SKEVM_BRD; RoHS: RoHS; Temperature: -55°C+125°C; Tolerance: 10%; Voltage: 10V; Wattage: NA; Weight: 400mg; Datasheet: Y:\MIS_DATABASE\DATASHEETS\CAPACITORS\293D_SER_MAR20.PDF
D1 D14 = DIODE_ZENER_SOT23_13: DIODE ZENER 250mW 6.8V SOT23-123; Chkd/date: MANIRAJA/031017; Crtd /date: MANIRAJA/031017; Custom_Duty: 15%; Customs_HS_Code: 85412900; Distributor_name: DIGIKEY; Distributor_part_number: BZX84C6V8LT1GOSCT-ND; Height: 1.11MM; Mfr_name: ON SEMICONDUCTOR; Mistral Part No: 130017100002-R; Package: SOT23-123; Part_type: DIODE\ZENER; Project: TI_MAXIE_CPB; RoHS: RoHS; Temperature: -65°C+150°C; Tolerance: NA; Voltage: 6.8V; Wattage: NA; Weight: 8mg; Datasheet: Y:\MIS_DATABASE\DATASHEETS\DISCRETES\DIODES\BZX84XX.PDF
J7 = CON_USB-A_4_2SH: CON USB-A TYPE 4POS FEMALE RT SMD; Chkd/date: MANIRAJA/271017; Crtd /date: MANIRAJA/271017; Custom_Duty: 24%; Customs_HS_Code: 85369090; Distributor_name: DIGIKEY; Distributor_part_number: 732-5969-1-ND; Height: 7.35MM; Mfr_name: WURTH ELECTRONICS; Mfr_part_number: 629104151021; Mistral Part No: 150017100042-R; Package: SMD; Part_type: CONNECTOR\USB; Project: TI_SVB_MAXWELL_SPM; RoHS: RoHS; Temperature: -40°C+85°C; Tolerance: NA; Voltage: NA; Wattage: NA; Weight: NA; Datasheet: Y:\MIS_DATABASE\DATASHEETS\CONNECTORS\629104151021.PDF
R68 R69 = RESISTOR: RES 499E 1/16W 1% 0402; Chkd/date: MANIRAJA/051020; Crtd /date: ALVY/051020; Custom_Duty: 15%; Customs_HS_Code: 85332119; Distributor_name: DIGIKEY; Distributor_part_number: 311-499LRCT-ND; Footprint Path: Y:\MIS_DATABASE\Library\ALTIUM_TOOL\PCB_FOOTPRINTS\Altium_Footprint_Lib.PcbLib; Height: 0.40MM; Library Path: Y:\MIS_DATABASE\Library\ALTIUM_TOOL\SCHEMATICS_PARTS\MS_DISCRETE_Library.schlib; Mfr_name: YAGEO AMERICA; Mfr_part_number: RC0402FR-07499RL; Mistral Part No: 110020080006-R; Package: 0402; Part_type: RESISTORS\FIXED; Project: AM64XX_EVM; RoHS: RoHS; Temperature: -55°C+155°C; Tolerance: 1%; Voltage: NA; Wattage: 1/16W; Weight: 0.65mg; Datasheet: Y:\MIS_DATABASE\DATASHEETS\RESISTORS\RCXXXXL-SER_MAR18.PDF
R152 R649 = RESISTOR: RES 3.48K 1/20W 1% 0201; Chkd/date: PRADEEP/281123; Crtd /date: TAMILARASU/071123; Custom_Duty: 15%; Customs_HS_Code: 85322990; Distributor_name: DIGIKEY; Distributor_part_number: P122951CT-ND; Footprint Path: Y:\MIS_DATABASE\Library\ALTIUM_TOOL\PCB_FOOTPRINTS\Altium_Footprint_Lib.PcbLib; Height: 0.26MM; Library Path: Y:\MIS_DATABASE\Library\ALTIUM_TOOL\SCHEMATICS_PARTS\MS_DISCRETE_Library.schlib; Mfr_name: PANASONIC-ECG; Mfr_part_number: ERJ-1GNF3481C; Mistral Part No: 110023110006-R; Package: 0201; Part_type: RESISTORS\FIXED; Project: AM62P SK; RoHS: RoHS; Temperature: -55°C+125°C; Tolerance: 0.01; Voltage: NA; Wattage: 1/20W; Weight: 0.15mg; Datasheet: Y:\MIS_DATABASE\DATASHEETS\RESISTORS\PAN-ERJSER_DEC22.PDF
R153 R648 = RESISTOR: RES 16.5K 1/16W 1% 0402; Chkd/date: ALVY/091220; Crtd /date: MANIRAJA/091220; Custom_Duty: 15%; Customs_HS_Code: 85332119; Distributor_name: DIGIKEY; Distributor_part_number: YAG3002CT-ND; Footprint Path: Y:\MIS_DATABASE\Library\ALTIUM_TOOL\PCB_FOOTPRINTS\Altium_Footprint_Lib.PcbLib; Height: 0.40MM; Library Path: Y:\MIS_DATABASE\Library\ALTIUM_TOOL\SCHEMATICS_PARTS\MS_DISCRETE_Library.schlib; Mfr_name: YAGEO AMERICA; Mfr_part_number: RC0402FR-0716K5L; Mistral Part No: 110020120011-R; Package: 0402; Part_type: RESISTORS\FIXED; Project: TI_AM243x LP EVM; RoHS: RoHS; Temperature: -55°C+155°C; Tolerance: 1%; Voltage: NA; Wattage: 1/16W; Weight: 0.65mg; Datasheet: Y:\MIS_DATABASE\DATASHEETS\RESISTORS\RCXXXXL-SER_MAR18.PDF
R156 R647 = RESISTOR: RES 10K 1/20W 1% 0201; Chkd/date: VASANTHA/270117; Crtd /date: MANIRAJA/270117; Custom_Duty: 15%; Customs_HS_Code: 85332119; Distributor_name: DIGIKEY; Distributor_part_number: 311-10.0KMCT-ND; Footprint Path: Y:\MIS_DATABASE\Library\ALTIUM_TOOL\PCB_FOOTPRINTS\Altium_Footprint_Lib.PcbLib; Height: 0.26MM; Library Path: Y:\MIS_DATABASE\Library\ALTIUM_TOOL\SCHEMATICS_PARTS\MS_DISCRETE_Library.schlib; Mfr_name: YAGEO AMERICA; Mfr_part_number: RC0201FR-0710KL; Mistral Part No: 110011040018-R; Package: 0201; Part_type: RESISTORS\FIXED; Project: GOLDEN-I LITE; RoHS: RoHS; Temperature: -55°C+125°C; Tolerance: 1%; Voltage: NA; Wattage: 1/20W; Weight: 0.17mg; Datasheet: Y:\MIS_DATABASE\DATASHEETS\RESISTORS\RCXXXXL-SER_MAR18.PDF
U34 = TPS2051BD_SOIC8: IC POWER DISTRIBUTION SWITCH SOIC8; Chkd/date: NAVEED/150714; Crtd /date: VASANTHA/190614; Custom_Duty: 15%; Customs_HS_Code: 85423100; Distributor_name: DIGIKEY; Distributor_part_number: 296-26911-5-ND; Footprint Path: Y:\MIS_DATABASE\Library\ALTIUM_TOOL\PCB_FOOTPRINTS\Altium_Footprint_Lib.PcbLib; Height: 1.75MM; Library Path: Y:\MIS_DATABASE\Library\ALTIUM_TOOL\SCHEMATICS_PARTS\MS_MISCPOWER_Library.schlib; Mfr_name: TEXAS INSTRUMENTS; Mistral Part No: 142014060011-R; Package: SOIC8; Part_type: ICS\POWER; Project: AEGIS_POM; RoHS: RoHS; Temperature: -40°C+125°C; Tolerance: NA; Voltage: NA; Wattage: NA; Weight: 72.6mg; Datasheet: Y:\MIS_DATABASE\DATASHEETS\MISC\REGULATORS\TPS2051BDBVR.PDF
U114 = TPD4S012DRY_SON6: IC 4CH ESD SOLUTION FOR USB-HS/USB OTG/USB CHARGER INTERFACE SON6; Chkd/date: MANIRAJA/040719; Crtd /date: BAVISH/190811; Custom_Duty: 15%; Customs_HS_Code: 85423100; Distributor_name: DIGIKEY; Distributor_part_number: 296-24244-1-ND; Footprint Path: Y:\MIS_DATABASE\Library\ALTIUM_TOOL\PCB_FOOTPRINTS\Altium_Footprint_Lib.PcbLib; Height: 0.60MM; Library Path: Y:\MIS_DATABASE\Library\ALTIUM_TOOL\SCHEMATICS_PARTS\MS_MISCINTERFACE_Library.schlib; Mfr_name: TEXAS INSTRUMENTS; Mistral Part No: 141011080022-R; Package: SON6; Part_type: ICS\INTERFACE; Project: ACRO_DM3730; RoHS: RoHS; Temperature: -40°C+85°C; Tolerance: NA; Voltage: NA; Wattage: NA; Weight: 3.2mg; Datasheet: Y:\MIS_DATABASE\DATASHEETS\ICS\INTERFACE\TPD4S012DRYR.PDF
U12 = AM62-EVM_BGA425: IC AM62 SoC MICROPROCESSOR BGA425; Chkd/date: ALVY/110621; Crtd /date: MANIRAJA/110621; Custom_Duty: 15%; Customs_HS_Code: 85423100; Distributor_name: NA; Distributor_part_number: NA; Footprint Path: Y:\MIS_DATABASE\Library\ALTIUM_TOOL\PCB_FOOTPRINTS\Altium_Footprint_Lib.PcbLib; Height: 0.65MM; Library Path: Y:\MIS_DATABASE\Library\ALTIUM_TOOL\SCHEMATICS_PARTS\MS_MICROPROCESSOR_Library.schlib; Mfr_name: TEXAS INSTRUMENTS; Mistral Part No: 141221060001; Package: BGA425; Part_type: ICS\DIGITAL\MICROPROCESSOR; Project: AM62_EVM_BRD; RoHS: NA; Temperature: NA; Tolerance: NA; Voltage: NA; Wattage: NA; Weight: NA; Datasheet: Y:\MIS_DATABASE\DATASHEETS\ICS\DIGITAL\MICROCONTROLLER\AM62-SoC_SVB.PDF

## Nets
DGND: C59.1 C93.1 C115.2 C303.2 C305.2 C321.2 C355.2 C356.2 C371.2 C372.2 C376.2 C377.1 C427.2 C536.1 C537.1 C549.2 D1.1(A) D4.2(ANODE) D5.1(GND) D10.2(ANODE) D14.1(A) J7.4(GND) J9.2 J9.7 J9.15 J9.20 J9.27 J13.A1(GND) J13.A12(GND) J13.B1(GND) J13.B12(GND) LD12.1(CATHODE) LD16.1(CATHODE) Q20.4(S1) Q20.7(S2) R68.2 R69.2 R77.2 R83.1 R156.2 R219.2 R402.1 R418.2 R647.2 R650.2 U17.8(GND) U20.4(GND) U34.1(GND) U78.1(GND) U78.2(GND) U78.3(GND) U78.7(GND) U114.4(GND) Y4.2(GND1) Y4.4(GND2) ; also on sheet 1 3 12 13 14 15 16 17 18 19 20 21 22 23 24 25 26 27 28 29 30 31 32 33 34 35 39 40 41 42 43 44 45
VBUS_5V0_TYPEA1: C355.1 C371.1 C549.1 J7.1(VCC) R649.2 TP120.1(TP) U34.6(OUT1) U34.7(OUT2) U34.8(OUT3) U114.6(VBUS)
VBUS_TYPEC2: J13.A4(VBUS1) J13.A9(VBUS2) J13.B4(VBUS3) J13.B9(VBUS4) R152.2 R227.2 U78.4(IN1) U78.5(IN2) U78.6(IN3) ; also on sheet 12
VCC_1V8: C321.1 R107.1 U20.1(VCCA) ; also on sheet 14 15 20 21 23 27 39 41 42 44
VCC_3V3_SYS: C93.2 C376.1 C377.2 J9.1 R403.1 R404.1 R420.2 R489.2 R614.1 R617.1 R790.1 U20.8(VCCB) ; also on sheet 3 12 14 15 16 20 21 22 24 25 26 27 28 29 31 32 33 34 35 39 40 41 42 43 44 45
VCC_5V0: C115.1 C356.1 U34.2(IN1) U34.3(IN2) ; also on sheet 12 13 17 35 43
BT_EN_SOC_3V3: U12.E8(MCU_SPI0_CS0) ; also on sheet 20
CAN_IO_3V3: C59.2 R400.2 U17.16(VCC) ; also on sheet 1 17 33
CONN_MCU_PORz: J9.28 R489.1 ; also on sheet 44
CONN_MCU_RESETz: J9.25 R420.1 ; also on sheet 45
EXP_GPIO0_14: U20.7(B1) ; also on sheet 35
EXP_GPIO0_14_LT: U20.2(A1) ; also on sheet 23
MCU_GPIO0_15: J9.10 U12.E5(MCU_MCAN1_TX)
MCU_GPIO0_16: J9.11 U12.D4(MCU_MCAN1_RX)
MCU_I2C0_SCL: J9.24 R404.2 R746.2
MCU_I2C0_SCL_RC: C536.2 R746.1 U12.A8(MCU_I2C0_SCL)
MCU_I2C0_SDA: J9.21 R403.2 R747.2
MCU_I2C0_SDA_RC: C537.2 R747.1 U12.D10(MCU_I2C0_SDA)
MCU_MCAN0_RX: J9.22 U12.B3(MCU_MCAN0_RX)
MCU_MCAN0_TX: J9.16 U12.D6(MCU_MCAN0_TX)
MCU_OSC0_XI: R87.2 R358.2 U12.B2(MCU_OSC0_XI)
MCU_OSC0_XO: R83.2 R355.2 U12.A3(MCU_OSC0_XO)
MCU_RESETSTATz: J9.23 TP21.1(TP) ; also on sheet 34 44
MCU_SAFETY_ERRORz_1V8: TP28.1(TP) U20.3(A2) ; also on sheet 44
MCU_SAFETY_ERRORz_3V3: J9.26 U20.6(B2)
MCU_SPI0_CLK: J9.18 R748.2
MCU_SPI0_CS1: J9.8 U12.B8(MCU_SPI0_CS1)
MCU_SPI0_D0: J9.6 U12.D9(MCU_SPI0_D0)
MCU_SPI0_D1: J9.4 U12.C9(MCU_SPI0_D1)
MCU_UART0_CTS: U12.A6(MCU_UART0_CTSN) U17.9(3A)
MCU_UART0_CTS_3V3: U17.11(3B1) ; also on sheet 33
MCU_UART0_CTS_CONN: J9.12 U17.10(3B2)
MCU_UART0_MUX_OE: R77.1 U17.15(~{OE})
MCU_UART0_MUX_SEL: J8.2 R402.2 U17.1(S)
MCU_UART0_RTS: U12.B6(MCU_UART0_RTSN) U17.12(4A)
MCU_UART0_RTS_3V3: U17.14(4B1) ; also on sheet 33
MCU_UART0_RTS_CONN: J9.17 U17.13(4B2)
MCU_UART0_RX_3V3: U17.2(1B1) ; also on sheet 33
MCU_UART0_RXD: U12.B5(MCU_UART0_RXD) U17.4(1A)
MCU_UART0_RXD_CONN: J9.13 U17.3(1B2)
MCU_UART0_TX_3V3: U17.5(2B1) ; also on sheet 33
MCU_UART0_TXD: U12.A5(MCU_UART0_TXD) U17.7(2A)
MCU_UART0_TXD_CONN: J9.19 U17.6(2B2)
PMIC_PGOOD: R616.1 ; also on sheet 15 44
SoC_CLKIN: R87.1 ; also on sheet 27
SoC_USB0_DM: L10.4(OUT2) R750.2 U12.AE11(USB0_DM)
SoC_USB0_DP: L10.1(IN1) R751.2 U12.AD11(USB0_DP)
SoC_USB0_DRVVBUS: U12.C20(USB0_DRVVBUS) ; also on sheet 12
SoC_USB0_VBUS: R153.1 R156.1 U12.AC11(USB0_VBUS)
SoC_USB1_DM: L9.1(IN1) R752.2 U12.AD10(USB1_DM)
SoC_USB1_DP: L9.4(OUT2) R753.2 U12.AE9(USB1_DP)
SoC_USB1_DRVVBUS: R791.1 U12.F18(USB1_DRVVBUS)
SoC_USB1_VBUS: R647.1 R648.1 U12.AB10(USB1_VBUS)
USB0_TYPEACONN1_DM: J7.2(D-) L9.2(IN2) R752.1 U114.2(D-)
USB0_TYPEACONN1_DP: J7.3(D+) L9.3(OUT1) R753.1 U114.1(D+)
USB_TYPEA_EARTH: C372.1 J7.SH1 J7.SH2 R418.1
USB_TYPEA_OC_INDICATION: R790.2 U34.5(~{OC}) ; also on sheet 41
USB_TYPEC2_EARTH: C427.1 J13.SH1 J13.SH2 J13.SH3 J13.SH4 R219.1
USBC_CONN2_CC1: D4.1(CATHODE) J13.A5(CC1) ; also on sheet 12
USBC_CONN2_CC2: D10.1(CATHODE) J13.B5(CC2) ; also on sheet 12
USBC_CONN2_DM: D5.3(IO2) J13.A7(D-_1) J13.B7(D-_2) L10.3(OUT1) R750.1
USBC_CONN2_DP: D5.2(IO1) J13.A6(D+_1) J13.B6(D+_2) L10.2(IN2) R751.1
N16906426: C305.1 R358.1 Y4.1
N16906432: C303.1 R355.1 Y4.3
N17031262: LD12.2(ANODE) R227.1
N17492093: R107.2 U20.5(OE)
N17492111: J8.1 R400.1
N17656162: R748.1 U12.A7(MCU_SPI0_CLK)
N17726648: D1.3(C) R152.1 R153.2
N19738714: LD16.2(ANODE) R614.2
N19738757: LD17.1(CATHODE) Q20.1(D1) Q20.2(D2) Q20.5(D3) Q20.6(D4) Q20.8(D5)
N19738770: Q20.3(G) R616.2
N19738786: LD17.2(ANODE) R617.2
N19880817: R68.1 U12.AC9(USB1_RCALIB)
N19880821: R69.1 U12.AE10(USB0_RCALIB)
N19885322: D14.3(C) R648.2 R649.1
N22860173: R650.1 R791.2 U34.4(EN)

Not connected (* = marked no-connect by the designer): D1 2(NC)*; D14 2(NC)*; J9 3* 5* 9* 14*; J13 A2(TX1+)* A3(TX1-)* A8(SBU1)* A10(RX2-)* A11(RX2+)* B2(TX2+)* B3(TX2-)* B8(SBU2)* B10(RX1-)* B11(RX1+)*; U114 3(ID)* 5(NC)*

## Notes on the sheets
sheet 36
- D-Note:
  MCU_I2C0
  A pull-up is recommended for open-drain output
  type I2C interfaces, irrespective of the IO usage
  or IO configuration. Refer to the Pin Connectivity
  Requirements table of the SoC datasheet.
- D-Note:
  Open-drain output type buffer I2C interfaces have slew rate
  requirement specified when pulled to 3.3 V. An RC is used
  to limit the slew rate
- D-Note:
  SoC IO buffers are off during reset.
  A parallel pull is recommended near
  to the attached device input that is
  being driven by the SoC IO
  (input does not float).
- SOC - MCU DOMAIN
- D-Note:
  Y2 recommended crystal part number:
  Change the part number of Y4 to
  ABM11W-25.0000MHZ-8-D1X-T3
  Update DNI caps C305 and C303 to 12 pF
- D-Note:
  No HFOSC0 registers are required to be changed. These registers should remain in their default state. Select the
  appropriate crystal circuit components that are compliant to the values defined in the MCU_OSC0 Crystal Circuit
  Requirements table. Read the Load Capacitance and Shunt Capacitance sections to select the appropriate crystal
  circuit components.
- D-Note:
  Refer to Applications, Implementation, and Layout section of
  the data sheet for clock routing guidelines as below:
  Clock Routing Guidelines - Oscillator Routing
- D-Note:
  MCU_OSC0 has been validated only with a 25 MHz clock source, so that is the only frequency supported. The datasheet shows
  MCU_OSC0 not starting until after the core voltage, because there are some cases where the oscillator may not start until
  VDD_CORE is valid. In most cases it will start as early as VDDS_OSC0, but this may not always be the case. This diagram in
  the datasheet is showing the maximum start-up time, which must include the case where the delay is based on VDD_CORE being
  valid.
- D-Note:
  XO should be grounded when
  an external oscillator is used.
  Refer to the SoC datasheet.
- D-Note:
  Connect the 25 MHz crystal directly to the SoC XI and XO pins (no
  series or parallel resistors are recommended). The internal
  oscillator implements AGC (Automatic Gain Control) for amplitude
  control. Match the SoC and the EPHY crystal specs.
- SOC-MCU HEADER
- D-Note:
  Any SoC IO that has a trace connected but not being
  driven actively needs to be connected to an external
  pull. When adding pull is not feasible, ensure that the
  traces are routed away from noisy signals.
- C
- Silk: MCU HDR
- SOC - MCU_UART0 MUX
- V.
- INPUT/OUTPUT
- OEn
- SEL
- An
- L
- L(DEFAULT)
- An=nB1
- SOC - FT4232
- L
- H
- An=nB2
- SOC - MCU HEADER
sheet 37
- USB0 TYPE-C DRP
- D-Note:
  Refer to the SK/EVM user's guide for the recommended power adapters.
  Using the recommended adapter is recommended for proper functioning of SK/EVM
  Reference Document:
  EVM User's Guide : https://www.ti.com/lit/pdf/SPRUJ40
  Reference section : Power Requirement
- D-Note:
  Provide provision to bypass the CMC using
  0R resistor for performance testing.
- D-Note:
  Add additional caps to VBUS_TYPEC2
- Silk: TYPE-C DRP
- Bypass option for L10
- 90E
- DLW21SZ900HQ2B
- Bypass option for L10
- POWER INDICATION LED: VBUS_TYPEC2
- C
- CAD Note: Stack R750 & R751
  footprints with L10.
- POWER RAIL LEDS
- V.
- V.
sheet 38
- USB1 - USB 2.0 TYPE-A
- D-Note:
  USBx_DRVVBUS  Pull-down is a DNI
  to implement wake-up from deep sleep.
  For Normal USB operation, there is an
  internal pull-down enabled during SoC reset.
  USBx_DRVVBUS external pulldown can
  be populated when wake-up from deep
  sleep is not  implemented.
- C
- D-Note:
  Provision to bypass the CMC using 0R resistor provided
  for testing the USB interface performance
- Bypass option for L9
- 90E
- 90E
- DLW21SZ900HQ2B
- Bypass option for L9
- C
- CAD Note:
  Stack R752 & R753
  footprints with L9.
- Silk: TYPE-A
- C
- D-Note:
  VBUS divider and VBUS supply connection to processor
  Connection of supply to USBx_VBUS pin is optional
  when USB interface is configured as Host
- D-Note:
  Refer to the USB VBUS Design Guidelines section of the
  SoC data sheet for implementing the VBUS voltage divider
